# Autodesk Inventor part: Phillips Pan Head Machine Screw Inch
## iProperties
HeadHeight: 0.110 in
Author: Administrator
Shininess: 70.0
PropertySet Name: _Private Model Information
Created: 2000-12
Part Number: Phillips Pan Head Machine Screw Inch
Document SubType Name: Modeling
Designer: Administrator
Material: Steel, High Strength Low Alloy
Control State: 0
Master: False
Checked Out: False
PropertySet Name: Design Tracking Control
Density: 7.84
Volumn: 0.0334175022831377
Area: 0.7931629180511741
PropertySet Name: Model Information
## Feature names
1. Revolution1
2. Extrusion1
3. Extrusion2
4. Extrusion3
5. Chamfer1
